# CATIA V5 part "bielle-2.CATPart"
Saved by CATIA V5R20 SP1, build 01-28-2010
Part number: bielle-2
Bounding box of the stored display mesh (mm): x -110.826 to 289.174, y -24.008 to 5.992, z -30 to 60
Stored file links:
  C:\Users\Manon\Desktop\IAO\Pieces\bielle-2.CATPart
  C:\Users\Manon\Desktop\IAO\assemblage\Assemblage_rlanglais.CATProduct
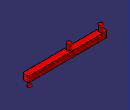
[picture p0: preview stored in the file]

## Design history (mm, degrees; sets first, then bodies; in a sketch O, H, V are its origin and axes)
External parameters (linked from other documents)
  External.bielle_2 = 360 mm
  External.bc = 200 mm
Body1 (main body)
  Sketch1 on xy-plane, origin (0, 0, 0), H (1, 0, 0), V (0, 1, 0)
    line L1 (-110.8262, 5.9921) -> (289.1738, 5.9921)
    line L2 (289.1738, 5.9921) -> (289.1738, -24.0079)
    line L3 (289.1738, -24.0079) -> (-110.8262, -24.0079)
    line L4 (-110.8262, -24.0079) -> (-110.8262, 5.9921)
    circle A1 centre (269.1738, -9.0079) radius 10
    point P5 (269.1738, -9.0079)
    circle A2 centre (69.1755, -10.088) radius 10
    point P6 (69.1755, -10.088)
    circle A3 centre (-90.8245, -10.0999) radius 10
    point P7 (-90.8245, -10.0999)
    length L4 = 30
    length L1 = 400
    radius A3 = 10
    radius A2 = 10
    radius A1 = 10
    distance P5 L3 = 15
    distance P5 L2 = 20
    distance P5 P7 = 360 {= External.bielle_2}
    distance P7 P6 = 160 {= External.bielle_2 -External.bc}
    horizontal: L1 H, L3 H
    vertical: L2 V, L4 V
  Pad1: profile Sketch1, direction (0, 0, 1), length 30
  Fillet1: radius 5, on edge [face of Pad1 from Sketch1.L3 | face of Pad1 from Sketch1.L4]; edge [face of Pad1 from Sketch1.L4 | face of Pad1 from Sketch1.L1]; edge [face of Pad1 from Sketch1.L2 | face of Pad1 from Sketch1.L3]; edge [face of Pad1 from Sketch1.L1 | face of Pad1 from Sketch1.L2]
  Sketch2 on end face of Pad1, origin (0, 0, 30), H (1, 0, 0), V (0, 1, 0)
    circle A1 centre (69.1755, -10.088) radius 10
    circle A2 centre (-90.8245, -10.0999) radius 10
    reference projected circle E1 centre (69.1755, -10.088) radius 10 from edge [end face of Pad1 | face of Pad1 from Sketch1.A2]
    reference projected circle E2 centre (-90.8245, -10.0999) radius 10 from edge [end face of Pad1 | face of Pad1 from Sketch1.A3]
    coincidence: E1 A1, A2 E2
  Pad2: profile Sketch2, direction (0, 0, 1), length 30, mirrored extent
  Sketch3 on face of Pad2, origin (0, 0, 0), H (1, 0, 0), V (0, -1, 0)
    circle A1 centre (269.1738, 9.0079) radius 10
    reference projected circle E1 centre (269.1738, 9.0079) radius 10 from edge [face of Pad1 from Sketch1.A1 | start face of Pad1]
    coincidence: A1 E1
  Pad3: profile Sketch3, direction (0, 0, -1), length 30, mirrored extent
